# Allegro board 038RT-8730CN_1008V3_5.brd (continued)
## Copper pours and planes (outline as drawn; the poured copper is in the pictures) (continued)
N27489618 on BOTTOM: 347.38,266.22 347.38,258.09 348.09,257.38 350.48,257.38 351.8,258.71 351.8,263.46 353.02,264.67 353.02,265.61 352.96,265.66 350.82,265.66 350.18,266.3 347.45,266.3
N27489634 on TOP: 343.8,274.63 343.8,258.01 344.71,257.09 350.1,257.09 351.43,258.42 351.43,263.81 352.59,264.97 352.59,274.92 350.13,277.38 346.55,277.38
N27489749 on BOTTOM: 364.01,283.29 365.17,283.29 365.5,282.96 368.85,282.96 368.99,282.82 368.99,281.72 368.81,281.54 364.16,281.54 363.71,282 363.71,282.98
N27489750 on BOTTOM: 358.7,290.49 358.7,290.48 358.32,290.1 358.32,288.04 358.7,287.66 359.72,287.66 360.03,287.35 360.03,284.56 360.48,284.1 365.97,284.1 366.34,283.73 369.72,283.73 370.1,284.1 370.1,286.94 369.7,287.33 366.88,287.33 366.61,287.6 366.61,289.97 366.1,290.49
N27489763 on TOP: 355.91,293.6 362.26,293.6 362.9,292.97 362.9,277.47 362.64,277.22 360.74,277.22 359.64,278.31 359.64,279.46 357.43,281.66 356.67,281.66 355.4,282.93 355.4,293.09
N27498479 on BOTTOM: 391.14,266.42 392.99,266.42 393.17,266.6 393.17,269.4 392.79,269.78 390.32,269.78 389.99,269.45 389.99,268.23 390.93,267.29 390.93,266.63
N27498509 on BOTTOM: 413.83,283.29 414.99,283.29 415.32,282.96 418.67,282.96 418.81,282.82 418.81,281.72 418.63,281.54 413.98,281.54 413.52,282 413.52,282.98
N27498510 on BOTTOM: 411.75,290.49 411.33,290.07 411.33,287.49 412.37,286.46 412.37,284.58 412.85,284.1 415.78,284.1 416.16,283.73 419.33,283.73 419.67,284.06 419.67,289.83 419.01,290.49
N27498525 on TOP: 408.41,292.89 408.41,277.6 408.79,277.22 412.8,277.22 413.56,277.98 413.56,286.74 413.82,287 415.72,287 416.23,287.51 416.23,292.97 415.6,293.6 409.12,293.6
N27498548 on BOTTOM: 387.38,266.22 387.38,258.09 388.09,257.38 390.48,257.38 391.8,258.71 391.8,263.46 393.02,264.67 393.02,265.61 392.96,265.66 390.82,265.66 390.18,266.3 387.45,266.3
N27498564 on TOP: 383.8,274.63 383.8,258.01 384.71,257.09 390.1,257.09 391.43,258.42 391.43,263.81 392.59,264.97 392.59,274.92 390.13,277.38 386.55,277.38
N27498679 on BOTTOM: 404.01,283.29 405.17,283.29 405.5,282.96 408.85,282.96 408.99,282.82 408.99,281.72 408.81,281.54 404.16,281.54 403.71,282 403.71,282.98
N27498680 on BOTTOM: 398.7,290.49 398.7,290.48 398.32,290.1 398.32,288.04 398.7,287.66 399.72,287.66 400.03,287.35 400.03,284.56 400.48,284.1 405.97,284.1 406.34,283.73 409.72,283.73 410.1,284.1 410.1,286.94 409.7,287.33 406.88,287.33 406.61,287.6 406.61,289.97 406.1,290.49
N27498693 on TOP: 395.91,293.6 402.26,293.6 402.9,292.97 402.9,277.47 402.64,277.22 400.74,277.22 399.64,278.31 399.64,279.46 397.43,281.66 396.67,281.66 395.4,282.93 395.4,293.09

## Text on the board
Ref Des/Silkscreen Bottom: #F-5 | #F-4 | #F-1 | #F | #E-5 | #E-4 | #E-1 | #E | #E-6 | #E-7 | #E-2 | #E-3 | #F-6 | #F-7 | #F-2 | #F-3 | #A | #D | #B-4 | #B | #A-4 | #D-4 | #B-5 | #B-1 | #A-5 | #D-5 | #A-1 | #D-1 | #A-6 | #D-6 | #B-6 | #B-2 | #A-2 | #D-2 | #A-7 | #D-7 | #B-7 | #B-3 | #A-3 | #D-3 | #C | #C-4 | #C-5 | #C-1 | #C-6 | #C-2 | #C-7 | #C-3
User.Comments: CR_1_17 | CR_1_16 | CR_1_20 | CR_1_18 | CR_123_3 | CR_123_2 | CR_1_19 | CR_1_22 | CR_1_23 | CR_110_2 | CR_1_1 | CR_111_9 | CR_33_5 | 129.00(3.23mm) | 229.00 | 104placesX129(+/-2)NPTH TOP SIDE | 85.00 | 229(+/-3) | 85(+/-6) | T-TYPE(TOP) | Y-TYPE(TOP) | NPTH | 5.2mm | 3.2 | 6.0 | 90 | BOT | TOP | Unit= mm | DUT QFN MIN PAD Width | 204.661mil | BOTTOM | 0.19 mm | 100mil | 72 mil | Cu | 122.232mil | FIGURE | SIZE | 72 | QTY | 20 | NOTES | T-TYPE | *PREPRAG THICKNESS= H | H | CORE | 126 | 129.0 | 12.0 | 25.0 | 8.01 | 8 | 12.01 | 4 | 104 | 192 | 2426 | 144 | 1895 | 1192 | Y-TYPE | VIA IN PAD
Ref Des/Silkscreen Top: 4.S1_I2C_SDA | 3.S1_I2C_SCL | 2.GND | 1.S1_VDD33 | 4.S0_I2C_SDA | 3.S0_I2C_SCL | 1.S0_VDD33 | 4.S4_I2C_SDA | 3.S4_I2C_SCL | 1.S4_VDD33 | BT_I2C | 1J3 | J3 | 4J3 | 4.S1_SIDD | 3.S1_SICK | 4.S0_SIDD | 3.S0_SICK | 4.S4_SIDD | 3.S4_SICK | SW2 | SIC | 1J1 | J1 | 4J1 | 4.S5_I2C_SDA | 3.S5_I2C_SCL | 1.S5_VDD33 | 5J3 | 4J4 | 4.S5_SIDD | 3.S5_SICK | SW3 | 5J1 | SW1 | 4J5 | 4J2 | 3.S4_UART_RX | 4.S4_UART_TX | UART | 1J4 | 4SW1 | 2.S0_ATX_VD33 | 4.S1_ATX_VD33 | 6.S2_ATX_VD33 | 8.S3_ATX_VD33 | 10.S4_ATX_VD33 | 12.S5_ATX_VD33 | 14.S6_ATX_VD33 | 16.S7_ATX_VD33 | ATX_VD33 | 4SW7 | #A | 4.S0_UART_TX | 3.S0_UART_RX | J2 | 4#A | #B | 4#B | J5 | J4 | 4.S1_UART_TX | 1J2 | 3.S1_UART_RX | 4SW3 | 5J5 | 5#A | 1#A | RTL8730A | 5J2 | 3.S5_UART_RX | 4.S5_UART_TX | 5#B | 1#B | 5J4 | 1J5 | 6#A | 2.S0_ATX_VD1V8 | 4.S1_ATX_VD1V8 | 6.S2_ATX_VD1V8 | 8.S3_ATX_VD1V8 | 10.S4_ATX_VD1V8 | 12.S5_ATX_VD1V8 | 14.S6_ATX_VD1V8 | 16.S7_ATX_VD1V8 | 2#A | ATX_VD1V8 | 6#B | 2#B | SW4 | SW7 | 6J4 | 7#A | 2J2 | 4.S2_UART_TX | 3.S2_UART_RX | 1.S2_VDD33 | 3#A | 7#B | 3#B | 2J5 | 3J4 | 4SW4 | 1.S3_VDD33 | 4.S3_UART_TX | 3.S3_UART_RX | 3J2 | 4SW2 | 1.S6_VDD33 | 6J5 | 3J5 | 6J2 | 3.S6_UART_RX | 4.S6_UART_TX | 1.S7_VDD33 | 7J5 | 7J4 | 7J2 | 3.S7_UART_RX | 4.S7_UART_TX | 3.S3_SICK | 4.S3_SIDD | 3J1 | 2J4 | 3.S3_I2C_SCL | 4.S3_I2C_SDA | 2.S0_ATX_VD0V9 | 4.S1_ATX_VD0V9 | 6.S2_ATX_VD0V9 | 8.S3_ATX_VD0V9 | 10.S4_ATX_VD0V9 | 12.S5_ATX_VD0V9 | 14.S6_ATX_VD0V9 | 16.S7_ATX_VD0V9 | ATX_VD0V9 | 3.S2_SICK | 4.S2_SIDD | 3.S6_SICK | 4.S6_SIDD | 3.S7_SICK | 4.S7_SIDD | 3J3 | 2J1 | 6J1 | 7J1 | 3.S6_I2C_SCL | 4.S6_I2C_SDA | 3.S7_I2C_SCL | 4.S7_I2C_SDA | 3.S2_I2C_SCL | 4.S2_I2C_SDA | 6J3 | 7J3 | 2J3 | PIN1->K9,1K9,2K9,3K9 | 8.NC | PIN2->K10,1K10,2K10,3K10 | 7.S4_PA16/ICFG3 | PIN3->K11,1K11,2K11,3K11 | 6.S4_PA15/ICFG2 | PIN4->K12,1K12,2K12,3K12 | 5.S4_PB11/ICFG1 | PIN5->K13,1K13,2K13,3K13 | 4.S4_PB10/ICFG0 | PIN6->K14,1K14,2K14,3K14 | 3.S4_PB21_BOOT_SEL_FLASH | PIN7->K15,1K15,2K15,3K15 | 2.S4_PB22_TEST_MODE_SEL | PIN8->K16,1K16,2K16,3K16 | 1.S4_CHIP_EN | PIN1->K18,1K18,2K18,3K18 | PIN2->K19,1K19,2K19,3K19 | PIN3->K20,1K20,2K20,3K20 | PIN4->K21,1K21,2K21,3K21 | PIN5->K22,1K22,2K22,3K22 | PIN6->K23,1K23,2K23,3K23 | PIN7->K25,1K25,2K25,3K25 | PIN8->K26,1K26,2K26,3K26 | PIN1->K1,1K1,2K1,3K1 | PIN2->K2,1K2,2K2,3K2 | PIN3->K3,1K3,2K3,3K3 | PIN4->K4,1K4,2K4,3K4 | PIN5->K5,1K5,2K5,3K5 | PIN6->K6,1K6,2K6,3K6 | PIN7->K7,1K7,2K7,3K7 | PIN8->K8,1K8,2K8,3K8 | 1.S1_CHIP_EN | 2.S1_PB22_TEST_MODE_SEL | 3.S1_PB21_BOOT_SEL_FLASH | 4.S1_PB10/ICFG0 | 5.S1_PB11/ICFG1 | 6.S1_PA15/ICFG2 | 7.S1_PA16/ICFG3 | PIN8->4K8,5K8,6K8,7K8 | PIN7->4K7,5K7,6K7,7K7 | PIN6->4K6,5K6,6K6,7K6 | PIN5->4K5,5K5,6K5,7K5 | PIN4->4K39,5K39,6K39,7K39 | PIN4->4K4,5K4,6K4,7K4 | PIN3->4K38,5K38,6K38,7K38 | PIN3->4K3,5K3,6K3,7K3 | PIN2->4K37,5K37,6K37,7K37 | PIN2->4K2,5K2,6K2,7K2 | PIN1->4K36,5K36,6K36,7K36 | PIN1->4K1,5K1,6K1,7K1 | 1.S0_CHIP_EN | 2.S0_PB22_TEST_MODE_SEL | PIN8->4K26,5K26,6K26,7K26 | 3.S0_PB21_BOOT_SEL_FLASH | PIN7->4K25,5K25,6K25,7K25 | 4.S0_PB10/ICFG0 | PIN6->4K23,5K23,6K23,7K23 | 5.S0_PB11/ICFG1 | PIN5->4K22,5K22,6K22,7K22 | 6.S0_PA15/ICFG2 | PIN4->4K21,5K21,6K21,7K21 | 7.S0_PA16/ICFG3 | PIN3->4K20,5K20,6K20,7K20 | PIN2->4K19,5K19,6K19,7K19 | PIN1->4K18,5K18,6K18,7K18 | 7.S5_PA16/ICFG3 | 6.S5_PA15/ICFG2 | 5.S5_PB11/ICFG1 | 4.S5_PB10/ICFG0 | 3.S5_PB21_BOOT_SEL_FLASH | 2.S5_PB22_TEST_MODE_SEL | 1.S5_CHIP_EN | PIN1->K28,1K28,2K28,3K28 | PIN2->K29,1K29,2K29,3K29 | 7.S6_PA16/ICFG3 | PIN3->K30,1K30,2K30,3K30 | PIN1->K36,1K36,2K36,3K36 | 6.S6_PA15/ICFG2 | PIN4->K31,1K31,2K31,3K31 | PIN2->K37,1K37,2K37,3K37 | 5.S6_PB11/ICFG1 | PIN5->K32,1K32,2K32,3K32 | PIN3->K38,1K38,2K38,3K38 | 4.S6_PB10/ICFG0 | PIN6->K33,1K33,2K33,3K33 | PIN4->K39,1K39,2K39,3K39 | 3.S6_PB21_BOOT_SEL_FLASH | PIN7->K34,1K34,2K34,3K34 | PIN5->KT1 | 2.S6_PB22_TEST_MODE_SEL | PIN8->K35,1K35,2K35,3K35 | 1.S6_CHIP_EN | 1.S3_CHIP_EN | 2.S3_PB22_TEST_MODE_SEL | 3.S3_PB21_BOOT_SEL_FLASH | PIN8->4K35,5K35,6K35,7K35 | 4.S3_PB10/ICFG0 | PIN7->4K34,5K34,6K34,7K34 | 5.S3_PB11/ICFG1 | PIN6->4K33,5K33,6K33,7K33 | 6.S3_PA15/ICFG2 | PIN5->4K32,5K32,6K32,7K32 | 7.S3_PA16/ICFG3 | PIN4->4K31,5K31,6K31,7K31 | PIN3->4K30,5K30,6K30,7K30 | PIN2->4K29,5K29,6K297K29 | PIN1->4K28,5K28,6K28,7K28 | PIN8->4K16,5K16,6K16,7K16 | PIN7->4K15,5K15,6K15,7K15 | PIN6->4K14,5K14,6K14,7K14 | PIN5->4K13,5K13,6K13,7K13 | PIN4->4K12,5K12,6K12,7K12 | PIN3->4K11,5K11,6K11,7K11 | PIN2->4K10,5K10,6K10,7K10 | PIN1->4K9,5K9,6K9,7K9 | 7.S7_PA16/ICFG3 | 6.S7_PA15/ICFG2 | 5.S7_PB11/ICFG1 | 4.S7_PB10/ICFG0 | 3.S7_PB21_BOOT_SEL_FLASH | 2.S7_PB22_TEST_MODE_SEL | 1.S7_CHIP_EN | 1.S2_CHIP_EN | 2.S2_PB22_TEST_MODE_SEL | 3.S2_PB21_BOOT_SEL_FLASH | 4.S2_PB10/ICFG0 | 5.S2_PB11/ICFG1 | 6.S2_PA15/ICFG2 | 7.S2_PA16/ICFG3 | PIN 1 | 25 | 100 | 26 | 76 | 50 | 75 | 51 | SITE4 | SITE0 | SITE5 | SITE1 | SITE6 | SITE2 | SITE7 | SITE3
DIMENSION: A1 | NPTH 1.63 x3 | M2 x4 | (0.0) | UNIT:MM | THICKNESS:4.94MM
User.8: HEIGHT:9.53MM | HEIGHT:1.4MM | HEIGHT:5.69MM | HEIGHT:1.6MM | HEIGHT:8MM | HEIGHT:10.16MM | HEIGHT:11.55MM | HEIGHT:6MM | HEIGHT:10MM | HEIGHT:0.9MM | HEIGHT:2.54MM | HEIGHT:0.6MM | UNIT:MM
User.9: Back DRILL (BOTTOM) | 201.73 MIL | BOTTOM | TOP | Cu | SIGNAL L5 | SIGNAL L7 | SIGNAL L9 | STUB MAX:20 mil | FIGURE | 6.2 | 6.3 | 6.4 | SIZE | 32 | 40 | QTY | NOTES | & VIA IN PAD | BACKDRILL FROM BOTTOM
User.10: HEIGHT:7MM | HEIGHT:8.6MM | HEIGHT:0.6MM | HEIGHT:0.71MM | HEIGHT:5.85MM | HEIGHT:10.29MM | HEIGHT:2MM | HEIGHT:2.24MM | HEIGHT:1.6MM | HEIGHT:2.8MM | HEIGHT:4MM | HEIGHT:1.27MM | HEIGHT:10MM | HEIGHT:1.55MM | HEIGHT:3.1MM | UNIT:MM
User.16: 254 | 249 | 250 | 255 | 226 | 228 | 227 | 225 | 224 | 13 | 14 | 16 | 248 | 251 | 17 | 22 | 18 | 19 | 15 | 12 | 146 | 147 | 98 | 97 | 136 | 137 | 140 | 141 | 142 | 150 | 144 | 145 | 99 | 96 | 143 | 8 | 9 | 127 | 126 | 121 | 100 | 123 | 122 | 120 | 28 | 29 | 253 | 252 | 247 | 245 | 244 | 239 | 231 | 230 | 229 | 235 | 234 | 10 | 11 | 24 | 20 | 21 | 23 | 152 | 151 | 138 | 139 | 134 | 135 | 148 | 149 | 156 | 157 | 133 | 5 | 6 | 7 | 111 | 101 | 125 | 124 | 117 | 116 | 103 | 102 | 107 | 106 | 119 | 242 | 246 | 240 | 236 | 233 | 232 | 243 | 25 | 30 | 241 | 238 | 237 | 27 | 31 | 26 | 129 | 132 | 130 | 131 | 158 | 159 | 154 | 153 | 128 | 155 | 0 | 1 | 4 | 2 | 3 | 114 | 112 | 108 | 105 | 110 | 115 | 109 | 104 | 118 | 113 | 195 | 194 | 193 | 192 | 196 | 219 | 218 | 222 | 217 | 216 | 40 | 44 | 45 | 46 | 47 | 48 | 49 | 54 | 50 | 51 | 177 | 91 | 41 | 223 | 172 | 173 | 176 | 168 | 169 | 174 | 175 | 182 | 178 | 179 | 95 | 94 | 89 | 88 | 67 | 66 | 68 | 64 | 90 | 65 | 199 | 197 | 220 | 213 | 212 | 207 | 203 | 202 | 198 | 42 | 43 | 37 | 38 | 39 | 56 | 52 | 53 | 55 | 60 | 221 | 181 | 171 | 71 | 61 | 215 | 165 | 166 | 183 | 167 | 184 | 180 | 188 | 189 | 170 | 92 | 87 | 85 | 93 | 84 | 79 | 70 | 69 | 75 | 74 | 210 | 208 | 200 | 205 | 204 | 190 | 33 | 36 | 34 | 35 | 62 | 63 | 58 | 59 | 211 | 209 | 206 | 214 | 185 | 191 | 32 | 57 | 201 | 163 | 187 | 160 | 161 | 164 | 162 | 186 | 83 | 82 | 86 | 81 | 80 | 77 | 78 | 76 | 73 | 72 | SPR2 | DGS1 | SPR1 | SPR3
User.17: NPTH1.62MMX4 | M25X4 | (0,0) | UNIT:MM | Thickness:5.2MM
User.19: CR1:(5.59,-23.17) | CR2:(26.13,-11.73) | UNIT:MM | A:(0,0) | A | CR1 | CR2 | RF1 | B | C | REFERENCE LINE | RF2
User.20: CR1:(-28.41,-23.17) | CR2:(-7.87,-11.73) | UNIT:MM | B:(0,0) | A | CR1 | CR2 | RF1 | B | C | REFERENCE LINE | RF2
User.21: CR1:(-28.41,10.83) | CR2:(-7.87,22.27) | UNIT:MM | C:(0,0) | A | CR1 | CR2 | RF1 | B | C | REFERENCE LINE | RF2
User.24: A1
User.27: Thickness:5.2MM | UNIT:MM
User.45: T-TYPE(TOP) | Y-TYPE(TOP) | GUIDE HOLE | VIA IN PAD | NOTES | FIGURE | SIZE | 8.0 | 8.01 | 12.0 | 12.01 | 16.0 | 25.0 | 40.0 | 41.0 | 41.31 | 53.0 | 72.0 | 75.0 | 169.0 | 63.5 | 64.0 | 70.0 | 126.0 | 128.0 | 129.0 | 137.8 | 277.0 | 114.0x63.0 | DRILL CHART: TOP to BOTTOM | ALL UNITS ARE IN MILS | TOLERANCE | +2.0/-2.0 | +3.0/-1.0 | +3.0/-3.0 | +3.0/-0.0 | +1.0/-1.0 | +2.0/-0.0 | PLATED | NON-PLATED | QTY | 1192 | 1863 | 32 | 192 | 2426 | 3494 | 144 | 282 | 8 | 2509 | 80 | 48 | 20 | 5 | 1 | 2 | 4 | 3 | 104 | 24
